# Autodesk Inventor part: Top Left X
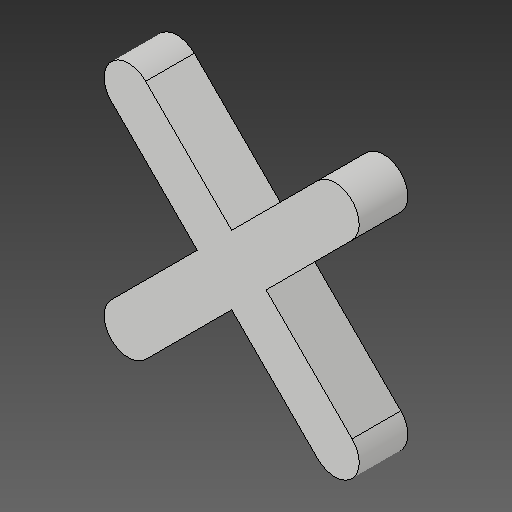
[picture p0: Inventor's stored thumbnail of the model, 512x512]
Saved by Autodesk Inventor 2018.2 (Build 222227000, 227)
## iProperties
Created: 2018-03
Part Number: Top Left X
Material: Generic
Document SubType Name: Modeling
Designer: PeterMaxwell-Stewart
Mass: 1.57135 g
Surface Area: 12.8562 cm^2
Volume: 1.57135 cm^3
Density: 1 g/cm^3
Appearance: Default
Author: PeterMaxwell-Stewart
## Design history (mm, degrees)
derived "O's and X's.ipt"
feature "Top Left X::O's and X's.ipt" dims "d0" = 10
tag "TaggingFeature1"
body "Solid1"
